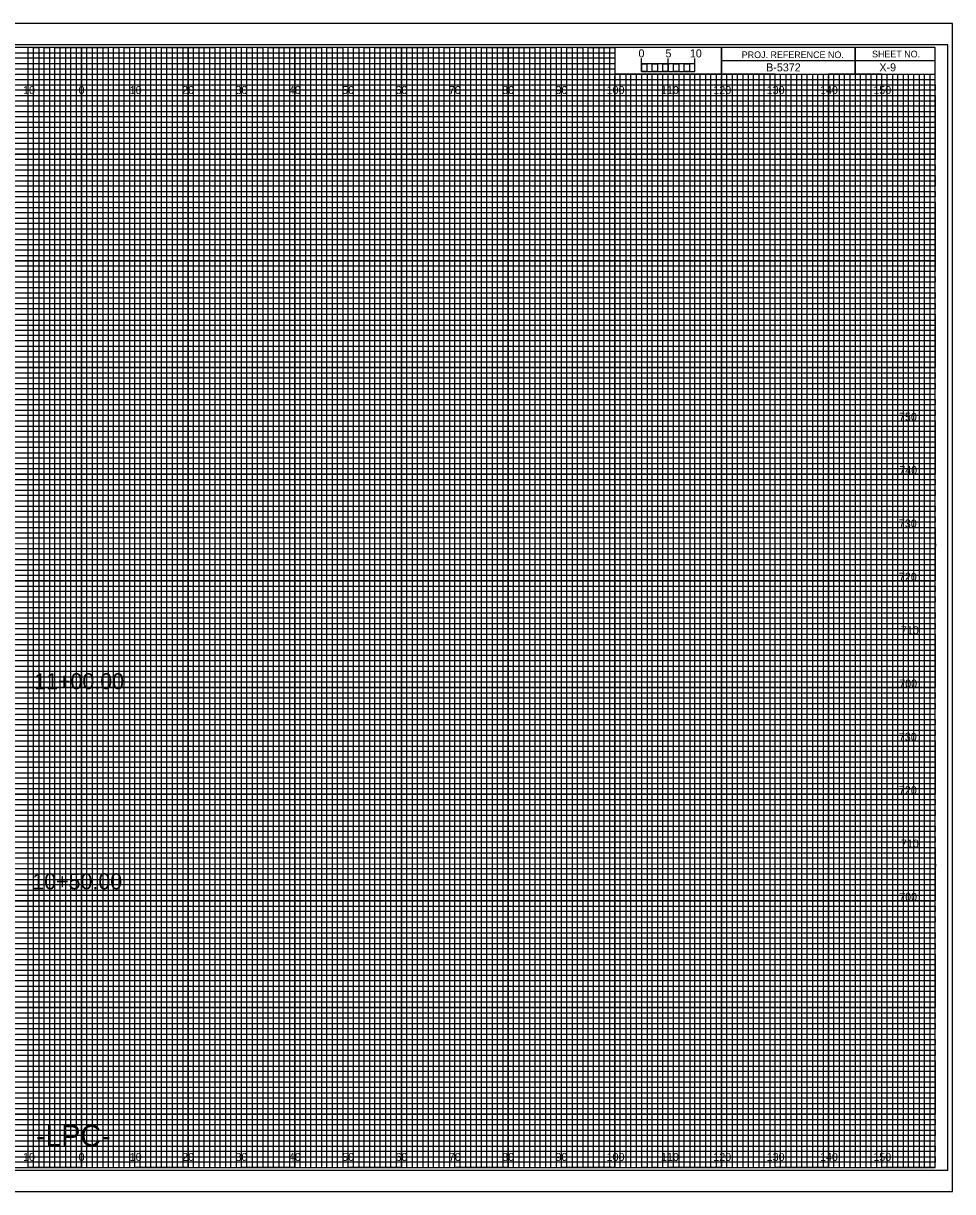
# Model space of a CAD drawing. Extents: x -397 to 323, y -4 to 654.
# Drawn here: x 149.1 to 323.3, y -4.5 to 214.5 of the extents above; entities that cross this region are included whole.
import ezdxf

# ---------------------------------------------------------------- set-up
doc = ezdxf.new("R2010")
doc.units = 0
for name, color, linetype in [('Default', 7, 'Continuous'), ('Prop XS Alignment Label', 7, 'Continuous'), ('Prop XS Bar Scale Labels', 7, 'Continuous'), ('Prop XS Elevation Labels', 7, 'Continuous'), ('Prop XS Offset Labels', 7, 'Continuous'), ('Prop XS Project Number', 7, 'Continuous'), ('Prop XS Sheet Number', 7, 'Continuous'), ('Prop XS Station Labels', 7, 'Continuous'), ('Sheet Cross Section CELL', 7, 'Continuous'), ('Sheet Cross Section Grid Major CELL', 7, 'Continuous'), ('Sheet Cross Section Grid Middle CELL', 7, 'Continuous'), ('Sheet Cross Section Grid Minor 1 CELL', 7, 'Continuous'), ('Sheet Cross Section Grid Minor 2 CELL', 7, 'Continuous'), ('Sheet Cross Section Scale CELL', 7, 'Continuous'), ('Sheet Cutting Line CELL', 7, 'Continuous'), ('Sheet DOT Grid CELL', 7, 'Continuous'), ('Sheet Plot Border Inside CELL', 7, 'Continuous'), ('Sheet Plot Border Outside CELL', 7, 'Continuous')]:
    doc.layers.add(name, color=color, linetype=linetype)

msp = doc.modelspace()

# ---------------------------------------------------------------- linework, layer by layer
at = {"layer": 'Default'}
msp.add_lwpolyline([(-13.4, -4.5), (323.3, -4.5), (323.3, 214.5), (-13.4, 214.5)], close=True, dxfattribs=at)
at = {"layer": 'Sheet Cross Section CELL'}
for p, q in [((305, 210), (305, 205)), ((305, 205), (305, 210)), ((280, 207.5), (280, 205)), ((320, 207.49), (280, 207.49)), ((280, 205), (320, 205))]:
    msp.add_line(p, q, dxfattribs=at)
for points in [[(320, 210), (0, 210), (0, 0), (320, 0)], [(280, 210), (260, 210), (260, 205.03), (280, 205.03)], [(320, 210), (280, 210), (280, 205), (320, 205)]]:
    msp.add_lwpolyline(points, close=True, dxfattribs=at)
at = {"layer": 'Sheet Cross Section Grid Major CELL'}
for p, q in [((150, 210), (140, 210)), ((150, 0), (150, 210)), ((170, 210), (160, 210)), ((160, 210), (160, 0)), ((170, 0), (170, 210)), ((190, 210), (180, 210)), ((180, 210), (180, 0)), ((190, 0), (190, 210)), ((210, 210), (200, 210)), ((200, 210), (200, 0)), ((210, 0), (210, 210)), ((230, 210), (220, 210)), ((220, 210), (220, 0)), ((230, 0), (230, 210)), ((250, 210), (240, 210)), ((240, 210), (240, 0)), ((250, 0), (250, 210)), ((260, 210), (260, 0)), ((270, 0), (270, 205)), ((290, 205), (280, 205)), ((280, 205), (280, 0)), ((290, 0), (290, 205)), ((310, 205), (300, 205)), ((300, 205), (300, 0)), ((310, 0), (310, 205)), ((160, 0), (150, 0)), ((180, 0), (170, 0)), ((200, 0), (190, 0)), ((220, 0), (210, 0)), ((240, 0), (230, 0)), ((260, 0), (250, 0)), ((280, 0), (270, 0)), ((300, 0), (290, 0)), ((320, 0), (310, 0)), ((320, 0), (320, 0))]:
    msp.add_line(p, q, dxfattribs=at)
for points in [[(0, 200), (320, 200), (320, 190), (0, 190)], [(0, 180), (320, 180), (320, 170), (0, 170)], [(0, 160), (320, 160), (320, 150), (0, 150)], [(0, 140), (320, 140), (320, 130), (0, 130)], [(0, 120), (320, 120), (320, 110), (0, 110)], [(0, 100), (320, 100), (320, 90), (0, 90)], [(0, 80), (320, 80), (320, 70), (0, 70)], [(0, 60), (320, 60), (320, 50), (0, 50)], [(0, 40), (320, 40), (320, 30), (0, 30)], [(0, 20), (320, 20), (320, 10), (0, 10)]]:
    msp.add_lwpolyline(points, dxfattribs=at)
at = {"layer": 'Sheet Cross Section Grid Middle CELL'}
for points in [[(145, 0), (155, 0), (155, 210), (165, 210), (165, 0), (175, 0), (175, 210), (185, 210), (185, 0), (195, 0), (195, 210), (205, 210), (205, 0), (215, 0), (215, 210), (225, 210), (225, 0), (235, 0), (235, 210), (245, 210), (245, 0), (255, 0), (255, 210), (259.93, 210), (260, 210), (260, 205), (264.99, 205), (264.99, 0), (275, 0), (275, 205), (285, 205), (285, 0), (295, 0), (295, 205), (305, 205), (305, 0), (315, 0), (315, 205)], [(0, 205), (275, 205)], [(0, 185), (320, 185), (320, 195), (0, 195)], [(0, 165), (320, 165), (320, 175), (0, 175)], [(0, 145), (320, 145), (320, 155), (0, 155)], [(0, 125), (320, 125), (320, 135), (0, 135)], [(0, 105), (320, 105), (320, 115), (0, 115)], [(0, 85), (320, 85), (320, 95), (0, 95)], [(0, 65), (320, 65), (320, 75), (0, 75)], [(0, 45), (320, 45), (320, 55), (0, 55)], [(0, 25), (320, 25), (320, 35), (0, 35)], [(0, 5), (320, 5), (320, 15), (0, 15)]]:
    msp.add_lwpolyline(points, dxfattribs=at)
at = {"layer": 'Sheet Cross Section Grid Minor 1 CELL'}
for p, q in [((0, 209), (260, 209)), ((260, 209), (260, 207.98)), ((260, 207.98), (0, 207.98)), ((0, 207), (260, 207)), ((260, 205.89), (0, 205.89)), ((260, 207), (260, 205.89)), ((0, 204), (320, 204))]:
    msp.add_line(p, q, dxfattribs=at)
for points in [[(0, 203), (270, 203), (320, 203), (320, 202), (0, 202)], [(0, 201), (320, 201), (320, 199), (0, 199)], [(0, 198), (320, 198), (320, 197), (0, 196.98)], [(0, 196), (320, 196), (320, 194), (0, 194)], [(0, 193), (320, 193), (320, 192), (0, 192)], [(0, 191), (320, 191), (320, 189), (0, 189)], [(0, 188), (320, 188), (320, 187), (0, 187)], [(0, 186), (320, 186), (320, 184), (0, 184)], [(0, 183), (320, 183), (320, 182), (0, 182)], [(0, 181), (320, 181), (320, 179), (0, 179)], [(0, 178), (320, 178), (320, 177), (0, 177)], [(0, 176), (320, 176), (320, 173.95), (320, 173), (320, 172), (0, 172)], [(0, 174), (320, 174), (320, 173), (0, 173)], [(0, 171), (320, 171), (320, 169), (0, 169.03)], [(0, 169.03), (320, 169), (320, 168), (0, 168)], [(0, 167), (320, 167), (320, 166), (0, 166)], [(0, 164), (320, 164), (320, 163), (0, 163)], [(0, 162), (320, 162), (320, 161), (0, 161)], [(-0.07, 158.89), (320, 158.89), (320, 157.88), (-0.07, 157.88)], [(0, 157), (320, 157), (320, 156), (0, 156)], [(0, 154), (320, 154), (320, 153), (0, 153)], [(0, 152), (320, 152), (320, 151), (0, 151)], [(0, 149), (320, 149), (320, 148), (0, 148)], [(0, 147), (320, 147), (320, 146), (0, 146)], [(0, 144), (320, 144), (320, 143), (0, 143)], [(0, 142), (320, 142), (320, 141), (0, 141)], [(0, 139), (320, 139), (319.99, 137.98), (0, 138)], [(0, 137), (320, 137), (320, 136), (0, 136)], [(0, 134), (320, 134), (320, 133), (0, 133)], [(0, 132), (320, 132), (320, 131), (0, 131)], [(0, 129), (320, 129), (320, 128), (0, 128)], [(0, 127), (320, 127), (320, 126), (0, 126)], [(0, 124), (320, 124), (320, 123), (0, 123)], [(0, 122), (320, 122), (320, 121), (0, 121)], [(0, 119), (320, 119), (320, 118), (0, 118)], [(0, 116.99), (320.07, 116.91), (320, 116), (0, 116)], [(0, 114), (320, 114), (320, 113), (0, 113)], [(0, 112), (320, 112), (320, 111), (0, 111)], [(0, 109), (320, 109), (320, 108), (0, 108)], [(0, 107), (320, 107), (320, 106), (0, 106)], [(0, 104), (320, 104), (320, 103), (0, 103)], [(0, 102), (320, 102), (320, 101), (0, 101)], [(0, 99), (320, 99), (320, 98), (0, 98)], [(0, 97), (320, 97), (320, 96), (0, 96)], [(0, 94), (320, 94), (320, 93), (0, 93)], [(0, 92), (320, 92), (320, 91), (0, 91)], [(0, 89), (320, 89), (320, 88), (0, 88)], [(0, 87), (320, 87), (320, 86), (0, 86)], [(0, 84), (320, 84), (320, 83), (0, 83)], [(0, 82), (320, 82), (320, 81), (0, 81)], [(0, 79), (320, 79), (319.99, 77.98), (0, 78)], [(0, 77), (320, 77), (320, 76), (0, 76)], [(0, 74), (320, 74), (320, 73), (0, 73)], [(0, 72), (320, 72), (320, 71), (0, 71)], [(0, 69), (320, 69), (320, 68), (0, 68)], [(0, 67), (320, 67), (320, 66), (0, 66)], [(0, 64), (320, 64), (320, 63), (0, 63)], [(0, 62), (320, 62), (320, 61), (0, 61)], [(0, 59), (320, 59), (320, 58), (0, 58)], [(0, 56.99), (320.07, 56.91), (320, 56), (0, 56)], [(0, 54), (320, 54), (320, 53), (0, 53)], [(0, 52), (320, 52), (320, 51), (0, 51)], [(0, 49), (320, 49), (320, 48), (0, 48)], [(0, 47), (320, 47), (320, 46), (0, 46)], [(0, 44), (320, 44), (320, 43), (0, 43)], [(0, 42), (320, 42), (320, 41), (0, 41)], [(0, 39), (320, 39), (320, 38), (0, 38)], [(0, 37), (320, 37), (320, 36), (0, 36)], [(0, 34), (320, 34), (320, 33), (0, 33)], [(0, 32), (320, 32), (320, 31), (0, 31)], [(0, 29), (320, 29), (320, 28), (0, 28)], [(0, 27), (320, 27), (320, 26), (0, 26)], [(0, 24), (320, 24), (320, 23), (0, 23)], [(0, 22), (320, 22), (320, 21), (0, 21)], [(0, 19), (320, 19), (320, 18), (0, 18)], [(0, 17), (320, 17), (320, 16), (0, 16)], [(0, 14), (320, 14), (320, 13), (0, 13)], [(0, 12), (320, 12), (320, 11), (0, 11)], [(0, 9), (320, 9), (320, 8), (0, 8)], [(0, 7), (320, 7), (320, 6), (0, 6)], [(0, 4), (320, 4), (320, 3), (0, 3)], [(0, 2), (320, 2), (320, 1), (0, 1)]]:
    msp.add_lwpolyline(points, dxfattribs=at)
at = {"layer": 'Sheet Cross Section Grid Minor 2 CELL'}
for p, q in [((267, 205), (266.01, 205)), ((266.01, 205), (266.01, 0)), ((267, 0), (267, 205)), ((269, 205), (268, 205)), ((268, 205), (268, 0)), ((269, 0), (269, 205)), ((266.01, 0), (265, 0)), ((268, 0), (267, 0))]:
    msp.add_line(p, q, dxfattribs=at)
for points in [[(150, 0), (151, 0), (151, 210), (152, 210), (152, 0)], [(152, 0), (153, 0), (153, 210), (154, 210), (154, 0)], [(155, 0), (156, 0), (156, 210), (157, 210), (157, 0)], [(157, 0), (158, 0), (158, 210), (159, 210), (159, 0)], [(160, 0), (161, 0), (161, 210), (162, 210), (162, 0)], [(162, 0), (163, 0), (163, 210), (164, 210), (164, 0)], [(165, 0), (166, 0), (166, 210), (167, 210), (167, 0)], [(167, 0), (168, 0), (168, 210), (169, 210), (169, 0)], [(170, 0), (171, 0), (171, 210), (172, 210), (172, 0)], [(172, 0), (173, 0), (173, 210), (174, 210), (174, 0)], [(175, 0), (176, 0), (176, 210), (177, 210), (177, 0)], [(177, 0), (178, 0), (178, 210), (179, 210), (179, 0)], [(180, 0), (181, 0), (181, 210), (182, 210), (182, 0)], [(182, 0), (183, 0), (183, 210), (184, 210), (184, 0)], [(185, 0), (186, 0), (186, 210), (187, 210), (187, 0)], [(187, 0), (188, 0), (188, 210), (189, 210), (189, 0)], [(190, 0), (191, 0), (191, 210), (192, 210), (192, 0)], [(192, 0), (193, 0), (193, 210), (194, 210), (194, 0)], [(195, 0), (196, 0), (196, 210), (197, 210), (197, 0)], [(197, 0), (198, 0), (198, 210), (199, 210), (199, 0)], [(200, 0), (201, 0), (201, 210), (202, 210), (202, 0)], [(202, 0), (203, 0), (203, 210), (204, 210), (204, 0)], [(205, 0), (206, 0), (206, 210), (207, 210), (207, 0)], [(207, 0), (208, 0), (208, 210), (209, 210), (209, 0)], [(210, 0), (211, 0), (211, 210), (212, 210), (212, 0)], [(212, 0), (213, 0), (213, 210), (214, 210), (214, 0)], [(215, 0), (216, 0), (216, 210), (217, 210), (217, 0)], [(217, 0), (218, 0), (218, 210), (219, 210), (219, 0)], [(220, 0), (221, 0), (221, 210), (222, 210), (222, 0)], [(222, 0), (223, 0), (223, 210), (224, 210), (224, 0)], [(225, 0), (226, 0), (226, 210), (227, 210), (227, 0)], [(227, 0), (228, 0), (228, 210), (229, 210), (229, 0)], [(230, 0), (231, 0), (231, 210), (232, 210), (232, 0)], [(232, 0), (233, 0), (233, 210), (234, 210), (234, 0)], [(235, 0), (236, 0), (236, 210), (237, 210), (237, 0)], [(237, 0), (238, 0), (238, 210), (239, 210), (239, 0)], [(240, 0), (241, 0), (241, 210), (242, 210), (242, 0)], [(242, 0), (243, 0), (243, 210), (244, 210), (244, 0)], [(245, 0), (246, 0), (246, 210), (247, 210), (247, 0)], [(247, 0), (248, 0), (248, 210), (249, 210), (249, 0)], [(250, 0), (251, 0), (251, 210), (252, 210), (252, 0)], [(252, 0), (253, 0), (253, 210), (254, 210), (254, 0)], [(255, 0), (256, 0), (256, 210), (257, 210), (257, 0)], [(257, 0), (258, 0), (258, 210), (259, 210), (259, 0)], [(260, 0), (261, 0), (261, 205), (262.02, 205), (262.02, 0)], [(262, 0), (263, 0), (263, 205), (263.99, 205), (263.99, 0)], [(270, 0), (270.98, 0), (270.98, 205), (272, 205), (272, 0)], [(272, 0), (273, 0), (273, 205), (274.05, 205), (274.05, 0)], [(275, 0), (276, 0), (276, 205), (277, 205), (277, 0)], [(277, 0), (278, 0), (278, 205), (279, 205), (279, 0)], [(280, 0), (281, 0), (281, 205), (282, 205), (282, 0)], [(282, 0), (283, 0), (283, 205), (284, 205), (284, 0)], [(285, 0), (286, 0), (286, 205), (287, 205), (287, 0)], [(287, 0), (288, 0), (288, 205), (289, 205), (289, 0)], [(290, 0), (291, 0), (291, 205), (292, 205), (292, 0)], [(292, 0), (293, 0), (293, 205), (294, 205), (294, 0)], [(295, 0), (296, 0), (296, 205), (297, 205), (297, 0)], [(297, 0), (298, 0), (298, 205), (299, 205), (299, 0)], [(300, 0), (301, 0), (301, 205), (302, 205), (302, 0)], [(302, 0), (303, 0), (303, 205), (304, 205), (304, 0)], [(305, 0), (306, 0), (306, 205), (307, 205), (307, 0)], [(307, 0), (308, 0), (308, 205), (309, 205), (309, 0)], [(310, 0), (311, 0), (311, 205), (312, 205), (312, 0)], [(312, 0), (313, 0), (313, 205), (314, 205), (314, 0)], [(315, 0), (316, 0), (316, 205), (317, 205), (317, 0)], [(317, 0), (318, 0), (318, 205), (319, 205), (319, 0)]]:
    msp.add_lwpolyline(points, dxfattribs=at)
at = {"layer": 'Sheet Cross Section Scale CELL'}
for p, q in [((265, 205.49), (265, 207.9)), ((265, 206.9), (265, 207.9)), ((270, 205.49), (270, 207.9)), ((275, 205.49), (275, 207.9)), ((275, 206.9), (275, 207.9))]:
    msp.add_line(p, q, dxfattribs=at)
for points in [[(275, 206.9), (265, 206.9), (265, 205.49), (275, 205.49)], [(265, 206.9), (266, 206.9), (266, 205.49), (265, 205.49)], [(267, 206.9), (268, 206.9), (268, 205.49), (267, 205.49)], [(269, 206.9), (270, 206.9), (270, 205.49), (269, 205.49)], [(271, 206.9), (272, 206.9), (272, 205.49), (271, 205.49)], [(273, 206.9), (274, 206.9), (274, 205.49), (273, 205.49)]]:
    msp.add_lwpolyline(points, close=True, dxfattribs=at)
at = {"layer": 'Sheet Cutting Line CELL'}
for p, q in [((323.3, 214.5), (-13.4, 214.5)), ((-13.4, -4.5), (323.3, -4.5))]:
    msp.add_line(p, q, dxfattribs=at)
at = {"layer": 'Sheet DOT Grid CELL'}
for p, q in [((150, 0), (150, 210)), ((160, 0), (160, 210)), ((170, 0), (170, 210)), ((180, 0), (180, 210)), ((190, 0), (190, 210)), ((200, 0), (200, 210)), ((210, 0), (210, 210)), ((220, 0), (220, 210)), ((230, 0), (230, 210)), ((240, 0), (240, 210)), ((250, 0), (250, 210)), ((260, 0), (260, 204.69)), ((270, 0), (270, 204.69)), ((280, 0), (280, 204.69)), ((290, 0), (290, 204.69)), ((300, 0), (300, 204.69)), ((310, 0), (310, 204.69)), ((0, 200), (320, 200)), ((0, 190), (320, 190)), ((0, 180), (320, 180)), ((0, 170), (320, 170)), ((0, 160), (320, 160)), ((0, 150), (320, 150)), ((0, 140), (320, 140)), ((0, 130), (320, 130)), ((0, 120), (320, 120)), ((0, 110), (320, 110)), ((0, 100), (320, 100)), ((0, 90), (320, 90)), ((0, 80), (320, 80)), ((0, 70), (320, 70)), ((0, 60), (320, 60)), ((0, 50), (320, 50)), ((0, 40), (320, 40)), ((0, 30), (320, 30)), ((0, 20), (320, 20)), ((0, 10), (320, 10))]:
    msp.add_line(p, q, dxfattribs=at)
at = {"layer": 'Sheet Plot Border Inside CELL'}
msp.add_lwpolyline([(-10.8, -0.5), (322.4, -0.5), (322.4, 210.5), (-10.8, 210.5)], close=True, dxfattribs=at)
at = {"layer": 'Sheet Plot Border Outside CELL'}
msp.add_lwpolyline([(-13.4, -4.5), (323.3, -4.5), (323.3, 214.5), (-13.4, 214.5)], close=True, dxfattribs=at)

# ---------------------------------------------------------------- texts
at = {"layer": 'Prop XS Alignment Label'}
msp.add_text('-LPC-', height=4, dxfattribs=at).set_placement((151.47, 4))
at = {"layer": 'Prop XS Bar Scale Labels'}
for s, p in [('5', (269.47, 208.12)), ('10', (274.04, 208.12))]:
    msp.add_text(s, height=1.5, dxfattribs=at).set_placement(p)
at = {"layer": 'Prop XS Elevation Labels'}
for s, p in [('750', (313.25, 140)), ('740', (313.3, 130)), ('730', (313.22, 120)), ('720', (313.23, 110)), ('710', (313.61, 100)), ('700', (313.28, 90)), ('730', (313.22, 80)), ('720', (313.23, 70)), ('710', (313.61, 60)), ('700', (313.28, 50))]:
    msp.add_text(s, height=1.5, dxfattribs=at).set_placement(p)
at = {"layer": 'Prop XS Offset Labels'}
for s, p in [('10', (149.04, 201.25)), ('0', (159.45, 201.25)), ('0', (159.45, 201.25)), ('10', (169.04, 201.25)), ('20', (178.86, 201.25)), ('30', (188.86, 201.25)), ('40', (198.86, 201.25)), ('50', (208.86, 201.25)), ('60', (218.86, 201.25)), ('70', (228.86, 201.25)), ('80', (238.86, 201.25)), ('90', (248.86, 201.25)), ('100', (258.44, 201.25)), ('110', (268.62, 201.25)), ('120', (278.44, 201.25)), ('130', (288.44, 201.25)), ('140', (298.44, 201.25)), ('150', (308.44, 201.25)), ('10', (149.04, 1.25)), ('0', (159.45, 1.25)), ('0', (159.45, 1.25)), ('10', (169.04, 1.25)), ('20', (178.86, 1.25)), ('30', (188.86, 1.25)), ('40', (198.86, 1.25)), ('50', (208.86, 1.25)), ('60', (218.86, 1.25)), ('70', (228.86, 1.25)), ('80', (238.86, 1.25)), ('90', (248.86, 1.25)), ('100', (258.44, 1.25)), ('110', (268.62, 1.25)), ('120', (278.44, 1.25)), ('130', (288.44, 1.25)), ('140', (298.44, 1.25)), ('150', (308.44, 1.25))]:
    msp.add_text(s, height=1.5, dxfattribs=at).set_placement(p)
at = {"layer": 'Prop XS Project Number'}
msp.add_text('B-5372', height=1.5, dxfattribs=at).set_placement((288.34, 205.5))
at = {"layer": 'Prop XS Sheet Number'}
msp.add_text('X-9', height=1.5, dxfattribs=at).set_placement((309.57, 205.5))
at = {"layer": 'Prop XS Station Labels'}
for s, p in [('11+00.00', (151.13, 89.68)), ('10+50.00', (150.77, 52.17))]:
    msp.add_text(s, height=3, dxfattribs=at).set_placement(p)
at = {"layer": 'Sheet Cross Section CELL'}
for s, p in [('PROJ. REFERENCE NO.', (283.77, 207.99)), ('SHEET NO.', (308.19, 208.12))]:
    msp.add_text(s, height=1.25, dxfattribs=at).set_placement(p)
at = {"layer": 'Sheet Cross Section Scale CELL'}
msp.add_text('0', height=1.5, dxfattribs=at).set_placement((264.41, 208.12))

doc.saveas('drawing.dxf')
